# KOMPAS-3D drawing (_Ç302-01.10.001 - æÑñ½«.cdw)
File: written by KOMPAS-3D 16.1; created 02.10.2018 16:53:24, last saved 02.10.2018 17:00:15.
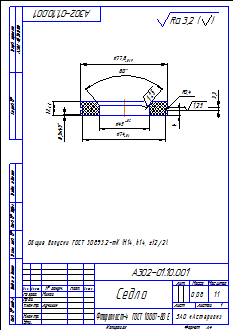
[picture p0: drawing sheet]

Sheet 1: A4, portrait

Title block, sheet 1: name: Седло; designation: А302-01.10.001; material: Фторопласт-4  ГОСТ 10007-80 Е; mass: 0,08; scale: 1:1; sheets: 1; organisation: ЗАО «Астерион»; sheet format: A4; drawn by: Милов; technical control: Лучихин

Views: Вид 1, Местный разрез 1, Спереди, Проекционный вид 2
Referenced files in Z:\Мембранные насосы\Мембранный электропривод\А302-00.00.000 - ASTRA-302 (МЭ200)\3Д ПВХ\: А302-01.10.001 - Седло.m3d
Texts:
  Общие допуски ГОСТ 30893.2-mK (H14, h14,  t2/2).
  Ra 3,2
  Ra 3,2 ( )
Dimensions and other numbers on the sheet: 74; 77,8; 45; 0,5; 3,3; 12; 1,25; 4; 0,4; 1:1; 1; 0,08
